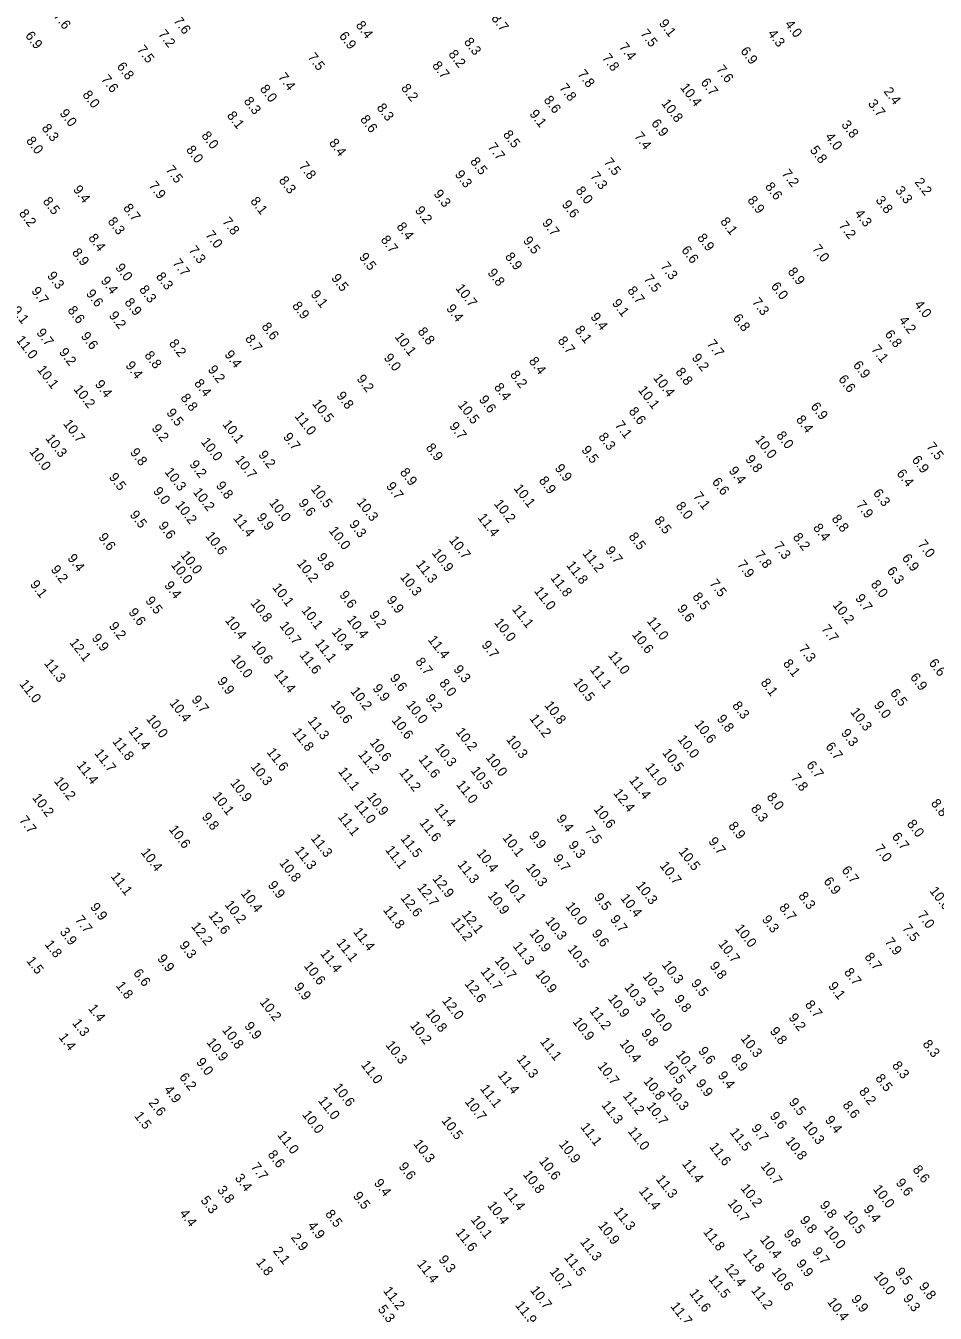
# Model space of a CAD drawing. Extents: x 815385 to 820851, y 582449 to 604245.
# Drawn here: x 819030 to 819500, y 593912 to 594576 of the extents above; entities that cross this region are included whole.
import ezdxf

# ---------------------------------------------------------------- set-up
doc = ezdxf.new("R2010")
doc.units = 0
for name, color, linetype in [('V-TOPO-SOUN-011609', 7, 'Continuous'), ('V-TOPO-SOUN-020509C', 7, 'Continuous'), ('V-TOPO-SOUN-EXCSS', 7, 'Continuous')]:
    doc.layers.add(name, color=color, linetype=linetype)

msp = doc.modelspace()

# ---------------------------------------------------------------- texts
at = {"layer": 'V-TOPO-SOUN-011609'}
for s, p in [('7.6', (819044.23, 594581.18)), ('7.6', (819106.09, 594578.69)), ('8.4', (819200.18, 594576.4)), ('8.7', (819270.11, 594580.05)), ('9.1', (819356.64, 594577.36)), ('4.0', (819421.62, 594576.93)), ('6.9', (819029.58, 594571.04)), ('7.2', (819098.19, 594571.84)), ('6.9', (819191.54, 594570.89)), ('7.5', (819347.02, 594572.06)), ('4.3', (819412.78, 594572.08)), ('7.5', (819087.29, 594563.81)), ('8.3', (819256.02, 594567.82)), ('7.4', (819336, 594565.16)), ('6.9', (819398.71, 594563.09)), ('7.5', (819175.34, 594559.93)), ('8.7', (819239.62, 594555.63)), ('8.2', (819247.99, 594561.46)), ('7.8', (819327.28, 594559.57)), ('7.6', (819068.77, 594548.54)), ('6.8', (819076.83, 594555.14)), ('7.4', (819160.09, 594549.63)), ('7.8', (819314.62, 594551.16)), ('7.6', (819386.19, 594553.64)), ('8.0', (819150.68, 594543.54)), ('8.2', (819223.51, 594543.97)), ('7.8', (819305.18, 594544.11)), ('10.4 ', (819367.6, 594544.31)), ('6.7', (819378.21, 594546.91)), ('2.4', (819472.59, 594542.28)), ('8.0', (819059.14, 594540.54)), ('8.3', (819142.38, 594537.24)), ('8.6', (819297.17, 594537.81)), ('10.8 ', (819357.87, 594536.13)), ('3.7', (819464.52, 594535.98)), ('9.0', (819047.32, 594530.95)), ('8.1', (819133.67, 594529.8)), ('8.3', (819210.97, 594533.88)), ('9.1', (819289.83, 594530.65)), ('8.3', (819038.06, 594523.3)), ('8.6', (819202.46, 594527.84)), ('6.9', (819352.66, 594525.78)), ('3.8', (819450.78, 594525.08)), ('8.0', (819030.01, 594516.78)), ('8.0', (819120.52, 594519.43)), ('8.4', (819186.36, 594515.67)), ('8.5', (819276.17, 594520.01)), ('7.4', (819343.87, 594519.09)), ('4.0', (819442.39, 594518.75)), ('8.0', (819112.57, 594512.14)), ('7.7', (819268.26, 594513.6)), ('5.8', (819434.54, 594511.97)), ('7.5', (819102.05, 594501.83)), ('7.8', (819170.79, 594503.73)), ('8.5', (819259.22, 594506.11)), ('7.5', (819328.13, 594505.75)), ('8.3', (819160.46, 594496.32)), ('9.3', (819251.32, 594499.41)), ('7.3', (819321.2, 594498.52)), ('7.2', (819420.01, 594499.83)), ('2.2', (819488.6, 594495.44)), ('7.9', (819093.26, 594493.63)), ('9.3', (819240.34, 594489.36)), ('8.0', (819313.67, 594491.01)), ('8.6', (819411.42, 594493.13)), ('3.3', (819478.6, 594491.17)), ('8.7', (819080.15, 594482.09)), ('8.1', (819145.78, 594485.64)), ('9.6', (819306.54, 594483.86)), ('8.9', (819402.31, 594486.09)), ('3.8', (819468.46, 594486.12)), ('7.8', (819131.28, 594475.06)), ('9.2', (819230.73, 594480.85)), ('4.3', (819457.66, 594479.24)), ('8.3', (819072.14, 594475.19)), ('7.0', (819122.57, 594468.2)), ('8.4', (819221.23, 594472.5)), ('9.7', (819296.36, 594474.38)), ('8.1', (819388.31, 594475.08)), ('7.2', (819449.43, 594473.04)), ('8.4', (819062.15, 594466.6)), ('8.7', (819213.03, 594465.71)), ('9.5', (819286.5, 594465.22)), ('8.9', (819376.37, 594466.71)), ('8.9', (819053.7, 594459.12)), ('7.3', (819113.9, 594460.31)), ('9.5', (819201.88, 594456.76)), ('8.9', (819277.19, 594456.95)), ('6.6', (819368.22, 594460.37)), ('7.0', (819435.72, 594461.07)), ('7.7', (819105.59, 594453.66)), ('7.3', (819357.42, 594451.97)), ('8.9', (819423.09, 594449.24)), ('9.3', (819040.88, 594447.09)), ('8.3', (819097.04, 594446.74)), ('9.5', (819187.54, 594445.93)), ('9.8', (819268.18, 594448.61)), ('7.5', (819348.81, 594445.48)), ('9.7', (819032.76, 594439.23)), ('8.3', (819088.4, 594439.99)), ('9.1', (819176.91, 594437.49)), ('10.7 ', (819251.62, 594440.72)), ('8.7', (819340.35, 594439.47)), ('6.0', (819414.44, 594441.67)), ('9.1', (819022.58, 594429.22)), ('8.9', (819080.84, 594433.39)), ('8.9', (819167.35, 594431.61)), ('9.4', (819246.87, 594430.23)), ('9.1', (819332.39, 594432.96)), ('7.3', (819404.64, 594433.54)), ('4.0', (819488.44, 594432.29)), ('9.2', (819072.76, 594426.58)), ('9.4', (819321.31, 594425.85)), ('6.8', (819394.82, 594425.27)), ('4.2', (819480.46, 594424.15)), ('9.6', (819058.31, 594415.93)), ('8.6', (819151.55, 594420.82)), ('8.8', (819232.1, 594418.37)), ('8.1', (819313.22, 594419.18)), ('6.8', (819473.17, 594416.94)), ('8.7', (819143.05, 594414.61)), ('10.1 ', (819220.26, 594415.64)), ('8.7', (819304.39, 594413.62)), ('7.7', (819381.35, 594411.98)), ('7.1', (819466.22, 594409.16)), ('9.2', (819047.04, 594407.65)), ('9.4', (819132.43, 594406.44)), ('9.0', (819214.64, 594404.78)), ('8.4', (819289.51, 594403.06)), ('9.2', (819373.59, 594404.72)), ('9.2', (819123.84, 594398.71)), ('8.2', (819279.82, 594396.03)), ('8.8', (819365.21, 594397.46)), ('6.9', (819456.82, 594401.01)), ('8.4', (819116.78, 594391.59)), ('9.2', (819200.61, 594393.91)), ('8.4', (819271.52, 594389.57)), ('10.4 ', (819353.7, 594394.43)), ('6.6', (819449.23, 594393.75)), ('8.8', (819109.72, 594384.1)), ('9.8', (819190.2, 594385.16)), ('9.6', (819263.73, 594383.2)), ('10.1 ', (819345.86, 594388.13)), ('9.5', (819102.43, 594376.39)), ('10.5 ', (819177.66, 594381.17)), ('10.5 ', (819252.85, 594380.46)), ('8.6', (819341.04, 594377.16)), ('6.9', (819434.95, 594379.63)), ('11.0 ', (819168.59, 594374.65)), ('9.7', (819248.47, 594369.47)), ('7.1', (819333.93, 594370.02)), ('8.4', (819427.37, 594372.9)), ('9.2', (819094.8, 594368.35)), ('9.7', (819162.67, 594363.91)), ('8.3', (819325.38, 594363.95)), ('8.0', (819417.26, 594364.69)), ('9.8', (819083.68, 594355.98)), ('8.9', (819236.32, 594358.4)), ('9.5', (819316.65, 594357.19)), ('10.0 ', (819406.25, 594362.56)), ('7.5', (819494.69, 594358.94)), ('10.7 ', (819137.89, 594352.17)), ('9.2', (819149.88, 594354.69)), ('9.8', (819401.21, 594352.42)), ('6.9', (819487.17, 594352.11)), ('8.9', (819222.96, 594345.66)), ('9.9', (819302.91, 594347.77)), ('9.4', (819392.7, 594346.5)), ('6.4', (819479.31, 594345.1)), ('9.8', (819128.02, 594338.8)), ('9.7', (819215.86, 594338.49)), ('10.1 ', (819281.72, 594337.4)), ('8.9', (819294.67, 594341.39)), ('6.6', (819384.05, 594340.74)), ('10.2 ', (819116.2, 594335.5)), ('10.3 ', (819200.63, 594330.24)), ('10.2 ', (819271.53, 594329.44)), ('7.1', (819374.3, 594333.35)), ('7.9', (819458.4, 594328.88)), ('6.3', (819467.14, 594334.95)), ('10.2 ', (819107.02, 594328.75)), ('8.0', (819365.28, 594328.26)), ('9.3', (819196.79, 594318.87)), ('11.4 ', (819263.09, 594322.28)), ('8.5', (819354.23, 594320.79)), ('8.4', (819436.18, 594317.03)), ('8.8', (819445.76, 594321.68)), ('10.0 ', (819186.26, 594315.55)), ('10.7 ', (819248.3, 594310.65)), ('8.5', (819341, 594312.47)), ('8.2', (819425.75, 594312.2)), ('10.9 ', (819239.46, 594304.07)), ('11.2 ', (819317.15, 594303.86)), ('9.7', (819328.98, 594305.34)), ('7.8', (819406.03, 594302.99)), ('7.3', (819415.82, 594307.67)), ('7.0', (819490.2, 594308.52)), ('10.2 ', (819169.76, 594298.68)), ('9.8', (819180.1, 594301.86)), ('11.3 ', (819231.17, 594298.28)), ('11.8 ', (819308.84, 594297.73)), ('7.9', (819396.98, 594298.08)), ('6.9', (819482.05, 594301.42)), ('10.3 ', (819223.02, 594291.68)), ('11.8 ', (819300.63, 594291.22)), ('6.3', (819474.3, 594294.76)), ('10.1 ', (819157.12, 594286.26)), ('11.0 ', (819292.21, 594284.43)), ('7.5', (819382.68, 594288.3)), ('8.0', (819465.96, 594287.86)), ('10.8 ', (819145.86, 594278.21)), ('9.9', (819216.09, 594279.74)), ('8.5', (819373.95, 594281.48)), ('10.2 ', (819446.3, 594277.21)), ('9.7', (819457.94, 594280.68)), ('10.4 ', (819195.55, 594269.68)), ('9.2', (819207.13, 594272.07)), ('11.1 ', (819280.85, 594275.12)), ('9.6', (819366.07, 594275.3)), ('10.4 ', (819187.79, 594263.28)), ('10.0 ', (819271.64, 594268.13)), ('11.0 ', (819350.43, 594268.88)), ('7.7', (819440.44, 594264.89)), ('11.1 ', (819179.14, 594257.46)), ('9.7', (819265.09, 594256.57)), ('10.6 ', (819342.71, 594261.94)), ('11.6 ', (819171.16, 594251.38)), ('11.0 ', (819330.41, 594251.23)), ('7.3', (819428.76, 594254.61)), ('9.3', (819250.6, 594243.98)), ('11.1 ', (819321.09, 594243.86)), ('8.1', (819420.68, 594247)), ('6.6', (819495.89, 594247.27)), ('8.0', (819243.25, 594236.85)), ('10.5 ', (819312.43, 594237.24)), ('8.1', (819409.12, 594237.08)), ('6.9', (819486.27, 594239.91)), ('6.5', (819475.98, 594231.79)), ('10.0 ', (819226.16, 594225.75)), ('9.2', (819236.12, 594229.05)), ('10.8 ', (819297.55, 594225.47)), ('8.3', (819394.47, 594225.24)), ('9.0', (819467.54, 594225.48)), ('10.6 ', (819218.67, 594217.76)), ('11.2 ', (819289.87, 594218.69)), ('9.8', (819386.52, 594218.45)), ('10.3 ', (819455.42, 594222.03)), ('10.6 ', (819375.01, 594215.63)), ('9.3', (819450.62, 594211.08)), ('10.6 ', (819207.38, 594206.24)), ('10.3 ', (819277.8, 594207.82)), ('10.0 ', (819366.28, 594207.93)), ('6.7', (819442.62, 594204.15)), ('11.2 ', (819201.35, 594200.12)), ('10.0 ', (819267.22, 594198.53)), ('10.5 ', (819358.35, 594200.97)), ('10.5 ', (819259.57, 594191.73)), ('11.0 ', (819349.54, 594193.52)), ('6.7', (819432.75, 594194.56)), ('11.0 ', (819251.98, 594184.57)), ('11.4 ', (819341.26, 594186.76)), ('7.8', (819424.7, 594188.01)), ('12.4 ', (819333.06, 594180.15)), ('8.0', (819412.25, 594178.14)), ('11.4 ', (819240.61, 594172.55)), ('10.6 ', (819323.02, 594171.76)), ('8.3', (819404.05, 594172.11)), ('8.8', (819497.02, 594174.89)), ('11.6 ', (819233.05, 594164.85)), ('8.9', (819392.44, 594163.19)), ('8.0', (819484.61, 594164.23)), ('7.5', (819318.37, 594160.78)), ('6.7', (819476.84, 594157.64)), ('9.3', (819309.91, 594153.29)), ('9.7', (819382.18, 594155.2)), ('7.0', (819467.94, 594151.51)), ('9.7', (819301.98, 594146.41)), ('10.5 ', (819366.79, 594149.94)), ('10.3 ', (819287.91, 594141.68)), ('10.7 ', (819357.05, 594142.69)), ('6.7', (819450.93, 594140.33)), ('10.1 ', (819276.97, 594133.52)), ('10.3 ', (819344.77, 594132.47)), ('6.9', (819441.63, 594134.62)), ('10.9 ', (819268.29, 594127.27)), ('10.4 ', (819336.76, 594125.93)), ('8.3', (819428.56, 594126.96)), ('10.0 ', (819496.31, 594129.64)), ('8.7', (819418.65, 594121.02)), ('7.0', (819490.01, 594117.15)), ('9.7', (819331.46, 594115.02)), ('10.0 ', (819395.89, 594110.31)), ('9.3', (819409.79, 594114.9)), ('7.5', (819482.18, 594110.37)), ('9.6', (819322.01, 594107.59)), ('7.9', (819473.13, 594103.38)), ('10.5 ', (819309.46, 594099.63)), ('10.7 ', (819387.24, 594102.29)), ('9.8', (819382.81, 594090.92)), ('8.7', (819462.74, 594095.55)), ('10.9 ', (819292.89, 594086.73)), ('8.7', (819452.21, 594087.67)), ('9.5', (819373.21, 594081.96)), ('9.1', (819444, 594080.53)), ('9.8', (819364.48, 594073.83)), ('8.7', (819432.02, 594070.98)), ('10.0 ', (819352.3, 594066.87)), ('9.2', (819423.55, 594064.25)), ('9.8', (819413.88, 594057.23)), ('10.4 ', (819336.31, 594050.9)), ('9.8', (819347.51, 594056.29)), ('10.3 ', (819398.81, 594053.49)), ('8.3', (819492.72, 594050.59)), ('10.7 ', (819324.96, 594039.26)), ('8.9', (819393.73, 594043.34)), ('8.3', (819476.98, 594039.55)), ('9.9', (819375.68, 594030.28)), ('9.4', (819386.99, 594034.38)), ('8.5', (819468.33, 594032.96)), ('10.3 ', (819360.94, 594026.13)), ('8.2', (819459.88, 594026.06)), ('10.7 ', (819350.15, 594018.54)), ('8.6', (819451.42, 594019.1)), ('9.4', (819442.32, 594011.42)), ('10.3 ', (819430.96, 594008.62)), ('10.8 ', (819421.89, 594000.59)), ('10.7 ', (819409.13, 593987.69)), ('8.6', (819487.57, 593985.85)), ('9.6', (819478.86, 593979)), ('10.2 ', (819398.81, 593976.22)), ('10.0 ', (819467.1, 593975.79)), ('10.7 ', (819392.08, 593968.44)), ('9.4', (819462.22, 593965.36)), ('10.5 ', (819451.8, 593962.48)), ('10.0 ', (819441.85, 593954.69)), ('9.9', (819427.46, 593937.27)), ('9.7', (819435.8, 593943.56)), ('10.6 ', (819414.84, 593933.09)), ('9.8', (819490.79, 593925.56)), ('9.3', (819482.63, 593919.37))]:
    msp.add_text(s, height=5, rotation=307.782, dxfattribs=at).set_placement(p)
at = {"layer": 'V-TOPO-SOUN-020509C'}
for s, p in [('11.0 ', (819024.8, 594414)), ('10.7 ', (819049.18, 594370.76)), ('10.3 ', (819040, 594363.22)), ('10.0 ', (819031.71, 594356.39)), ('9.5', (819083.53, 594323.76)), ('9.6', (819067.34, 594312.2)), ('10.0 ', (819109.72, 594302.97)), ('9.4', (819051.37, 594301.35)), ('10.0 ', (819104.81, 594297.9)), ('9.2', (819042.78, 594295.49)), ('9.1', (819032.09, 594287.83)), ('9.4', (819101.34, 594287.32)), ('9.5', (819091.58, 594279.41)), ('9.6', (819082.88, 594273.41)), ('9.2', (819072.76, 594266.31)), ('12.1 ', (819052.42, 594257.84)), ('9.9', (819063.87, 594260.15)), ('10.6 ', (819146.25, 594256.54)), ('11.3 ', (819039.36, 594247.11)), ('10.0 ', (819135.78, 594249.35)), ('11.0 ', (819026.61, 594236.48)), ('9.9', (819128.67, 594237.87)), ('10.4 ', (819104.02, 594226.61)), ('9.7', (819115.42, 594228.33)), ('10.0 ', (819092.07, 594218.42)), ('11.3 ', (819175.33, 594217.51)), ('11.4 ', (819082.95, 594212.27)), ('11.8 ', (819167.39, 594211.56)), ('11.8 ', (819074.56, 594206.79)), ('11.7 ', (819065.26, 594200.72)), ('11.6 ', (819154.22, 594201.28)), ('11.4 ', (819056.12, 594194.53)), ('10.3 ', (819145.95, 594193.81)), ('10.2 ', (819044.45, 594186.34)), ('10.9 ', (819135.39, 594185.35)), ('10.2 ', (819033.2, 594177.76)), ('10.1 ', (819126.22, 594178.6)), ('10.9 ', (819205.9, 594178.31)), ('11.0 ', (819199.4, 594174.19)), ('7.7', (819026.44, 594166.13)), ('9.8', (819120.71, 594167.88)), ('11.1 ', (819191.01, 594167.84)), ('10.6 ', (819103.73, 594161.41)), ('11.3 ', (819176.97, 594156.83)), ('11.3 ', (819168.72, 594150.46)), ('10.4 ', (819089.24, 594149.54)), ('10.8 ', (819160.73, 594144.08)), ('11.1 ', (819073.72, 594137.19)), ('9.9', (819154.8, 594132.62)), ('12.7 ', (819231.84, 594131.44)), ('12.9 ', (819239.74, 594135.97)), ('10.4 ', (819140.86, 594128.37)), ('12.6 ', (819223.29, 594126.06)), ('9.9', (819063.12, 594121.3)), ('12.6 ', (819124.12, 594117.05)), ('10.2 ', (819132.5, 594122.56)), ('11.8 ', (819214.26, 594119.84)), ('7.7', (819055.29, 594114.74)), ('12.2 ', (819115.23, 594111.39)), ('3.9', (819047.38, 594108.52)), ('11.4 ', (819198.85, 594108.52)), ('1.8', (819039.66, 594102.05)), ('9.3', (819109.11, 594101.58)), ('11.4 ', (819181.81, 594097.32)), ('11.1 ', (819190.18, 594102.87)), ('1.5', (819030.18, 594093.59)), ('9.9', (819097.71, 594094.72)), ('10.6 ', (819173.39, 594090.94)), ('10.7 ', (819271.86, 594093.7)), ('6.6', (819085.35, 594087.23)), ('11.7 ', (819264.55, 594088.08)), ('1.8', (819076.38, 594080.76)), ('9.9', (819168.24, 594080.11)), ('12.6 ', (819256.32, 594081.75)), ('10.2 ', (819150.61, 594072.27)), ('12.0 ', (819244.72, 594072.98)), ('1.4', (819062.07, 594068.96)), ('10.8 ', (819236.18, 594066.56)), ('1.3', (819053.84, 594061.42)), ('10.8 ', (819131.18, 594057.88)), ('9.9', (819142.71, 594059.86)), ('10.2 ', (819228.18, 594060.27)), ('1.4', (819046.86, 594054.12)), ('10.9 ', (819123.16, 594051.54)), ('11.1 ', (819295.27, 594051.9)), ('10.3 ', (819215.57, 594050.12)), ('9.0', (819117.78, 594041.31)), ('11.0 ', (819202.86, 594039.89)), ('11.3 ', (819283.19, 594042.87)), ('6.2', (819109.08, 594033.57)), ('11.4 ', (819273.4, 594034.63)), ('4.9', (819101.19, 594027.02)), ('10.6 ', (819188.52, 594028.18)), ('11.1 ', (819264.35, 594027.6)), ('2.6', (819093.26, 594020.32)), ('11.0 ', (819180.74, 594021.42)), ('10.7 ', (819256.46, 594020.88)), ('11.3 ', (819326.96, 594019.16)), ('1.5', (819085.85, 594013.54)), ('10.0 ', (819172.49, 594014.23)), ('10.5 ', (819244.4, 594011.1)), ('11.1 ', (819316.14, 594007.83)), ('11.0 ', (819159.66, 594003.7)), ('10.3 ', (819229.89, 593999.14)), ('10.9 ', (819304.99, 593998.91)), ('8.6', (819154.7, 593993.63)), ('7.7', (819145.99, 593987.21)), ('9.6', (819222.27, 593987.41)), ('10.6 ', (819294.7, 593990.23)), ('3.4', (819137.75, 593981.45)), ('9.4', (819209.56, 593978.85)), ('10.8 ', (819286.48, 593983.3)), ('11.3 ', (819355.07, 593980.88)), ('3.8', (819128.66, 593975.28)), ('9.5', (819198.72, 593972.2)), ('11.4 ', (819276.41, 593974.46)), ('11.4 ', (819346.29, 593974.75)), ('5.3', (819120.09, 593969.98)), ('10.4 ', (819268.08, 593967.37)), ('11.3 ', (819333.35, 593964.19)), ('4.4', (819109.2, 593963.2)), ('8.5', (819184.42, 593962.9)), ('10.1 ', (819259.56, 593959.96)), ('2.9', (819166.75, 593950.75)), ('4.9', (819175.33, 593956.82)), ('11.6 ', (819251.68, 593953.37)), ('10.9 ', (819325.21, 593956.98)), ('2.1', (819157.46, 593943.82)), ('11.3 ', (819315.97, 593948.49)), ('1.8', (819148.7, 593937.93)), ('9.3', (819242.9, 593939.4)), ('11.5 ', (819307.66, 593940.56)), ('11.4 ', (819231.75, 593937.12)), ('10.7 ', (819300.21, 593933.2)), ('12.4 ', (819390.38, 593935.21)), ('11.5 ', (819382.29, 593929.25)), ('11.2 ', (819214.33, 593923.25)), ('10.7 ', (819290.18, 593923.6)), ('11.6 ', (819372.3, 593922.09)), ('5.3', (819211.55, 593913.73)), ('11.9 ', (819282.5, 593915.83)), ('11.7 ', (819362.58, 593915.28))]:
    msp.add_text(s, height=5, rotation=307.782, dxfattribs=at).set_placement(p)
at = {"layer": 'V-TOPO-SOUN-EXCSS'}
for s, p in [('9.4', (819054.27, 594491.59)), ('8.5', (819038.67, 594485.54)), ('8.2', (819026.34, 594479.28)), ('9.0', (819076.07, 594451.27)), ('9.4', (819068.55, 594444.54)), ('9.6', (819060.96, 594437.89)), ('8.6', (819051.41, 594429.34)), ('9.7', (819035.34, 594417.7)), ('8.2', (819103.77, 594412.2)), ('8.8', (819091.1, 594406.06)), ('10.1 ', (819035.71, 594398.65)), ('9.4', (819081.33, 594400.79)), ('9.4', (819065.55, 594391.12)), ('10.2 ', (819054.52, 594388.63)), ('10.1 ', (819131.35, 594370.47)), ('10.0 ', (819120.26, 594361.37)), ('9.2', (819114.34, 594349.73)), ('9.5', (819072.77, 594343.17)), ('10.3 ', (819101.52, 594345.9)), ('9.0', (819095.57, 594335.9)), ('10.5 ', (819177.02, 594337.1)), ('10.0 ', (819155.45, 594329.95)), ('9.6', (819170.56, 594329.79)), ('9.6', (819098.28, 594318.1)), ('11.4 ', (819136.77, 594322.13)), ('9.9', (819148.99, 594322.48)), ('10.6 ', (819122.55, 594312.86)), ('9.6', (819191.72, 594282.36)), ('10.1 ', (819172.15, 594274.49)), ('10.4 ', (819132.69, 594269.33)), ('10.7 ', (819160.82, 594266.55)), ('11.4 ', (819237.43, 594259.25)), ('8.7', (819230.94, 594247.89)), ('11.4 ', (819157.98, 594241.65)), ('9.6', (819217.78, 594239.48)), ('10.2 ', (819197.38, 594232.72)), ('9.9', (819208.86, 594234.2)), ('10.6 ', (819187.24, 594225.78)), ('10.2 ', (819251.75, 594211.72)), ('10.3 ', (819241.05, 594203.59)), ('11.6 ', (819232.5, 594197.69)), ('11.1 ', (819191.05, 594191.32)), ('11.2 ', (819222.59, 594190.79)), ('9.4', (819303.74, 594166.9)), ('11.5 ', (819223.26, 594156.65)), ('10.1 ', (819275.9, 594157.08)), ('9.9', (819289.55, 594158.2)), ('11.1 ', (819215.4, 594150.85)), ('10.4 ', (819262.53, 594149.1)), ('11.3 ', (819252.64, 594143.29)), ('9.5', (819323.12, 594126.35)), ('12.1 ', (819254.92, 594117.45)), ('10.0 ', (819308.45, 594121.76)), ('11.2 ', (819249.32, 594113.56)), ('10.3 ', (819297.95, 594114.07)), ('10.9 ', (819289.77, 594107.8)), ('11.3 ', (819281.28, 594101.22)), ('10.3 ', (819358.2, 594091.5)), ('10.2 ', (819348.23, 594085.7)), ('10.3 ', (819338.83, 594079.86)), ('10.9 ', (819330.31, 594074.11)), ('11.2 ', (819320.78, 594067.76)), ('10.9 ', (819312.13, 594062.2)), ('10.1 ', (819365.32, 594045.21)), ('9.6', (819376.93, 594047.01)), ('10.5 ', (819359.22, 594039.79)), ('10.8 ', (819348.63, 594031.47)), ('11.2 ', (819338.03, 594024)), ('9.5', (819423.65, 594020.58)), ('9.6', (819413.82, 594013.47)), ('11.0 ', (819340.6, 594005.59)), ('11.5 ', (819393.2, 594005.15)), ('9.7', (819404.3, 594007.16)), ('11.6 ', (819382.66, 593997.61)), ('11.4 ', (819368.55, 593988.84)), ('9.8', (819439.6, 593967.5)), ('9.8', (819429.36, 593959.74)), ('11.8 ', (819379.52, 593953.67)), ('9.8', (819421.03, 593952.71)), ('10.4 ', (819408.77, 593949.74)), ('11.8 ', (819400, 593942.78)), ('10.0 ', (819467.5, 593930.96)), ('9.5', (819478.5, 593933.07)), ('11.2 ', (819404.27, 593923.54)), ('10.4 ', (819443.47, 593917.56)), ('9.9', (819455.88, 593918.97))]:
    msp.add_text(s, height=5, rotation=307.782, dxfattribs=at).set_placement(p)

doc.saveas('drawing.dxf')
